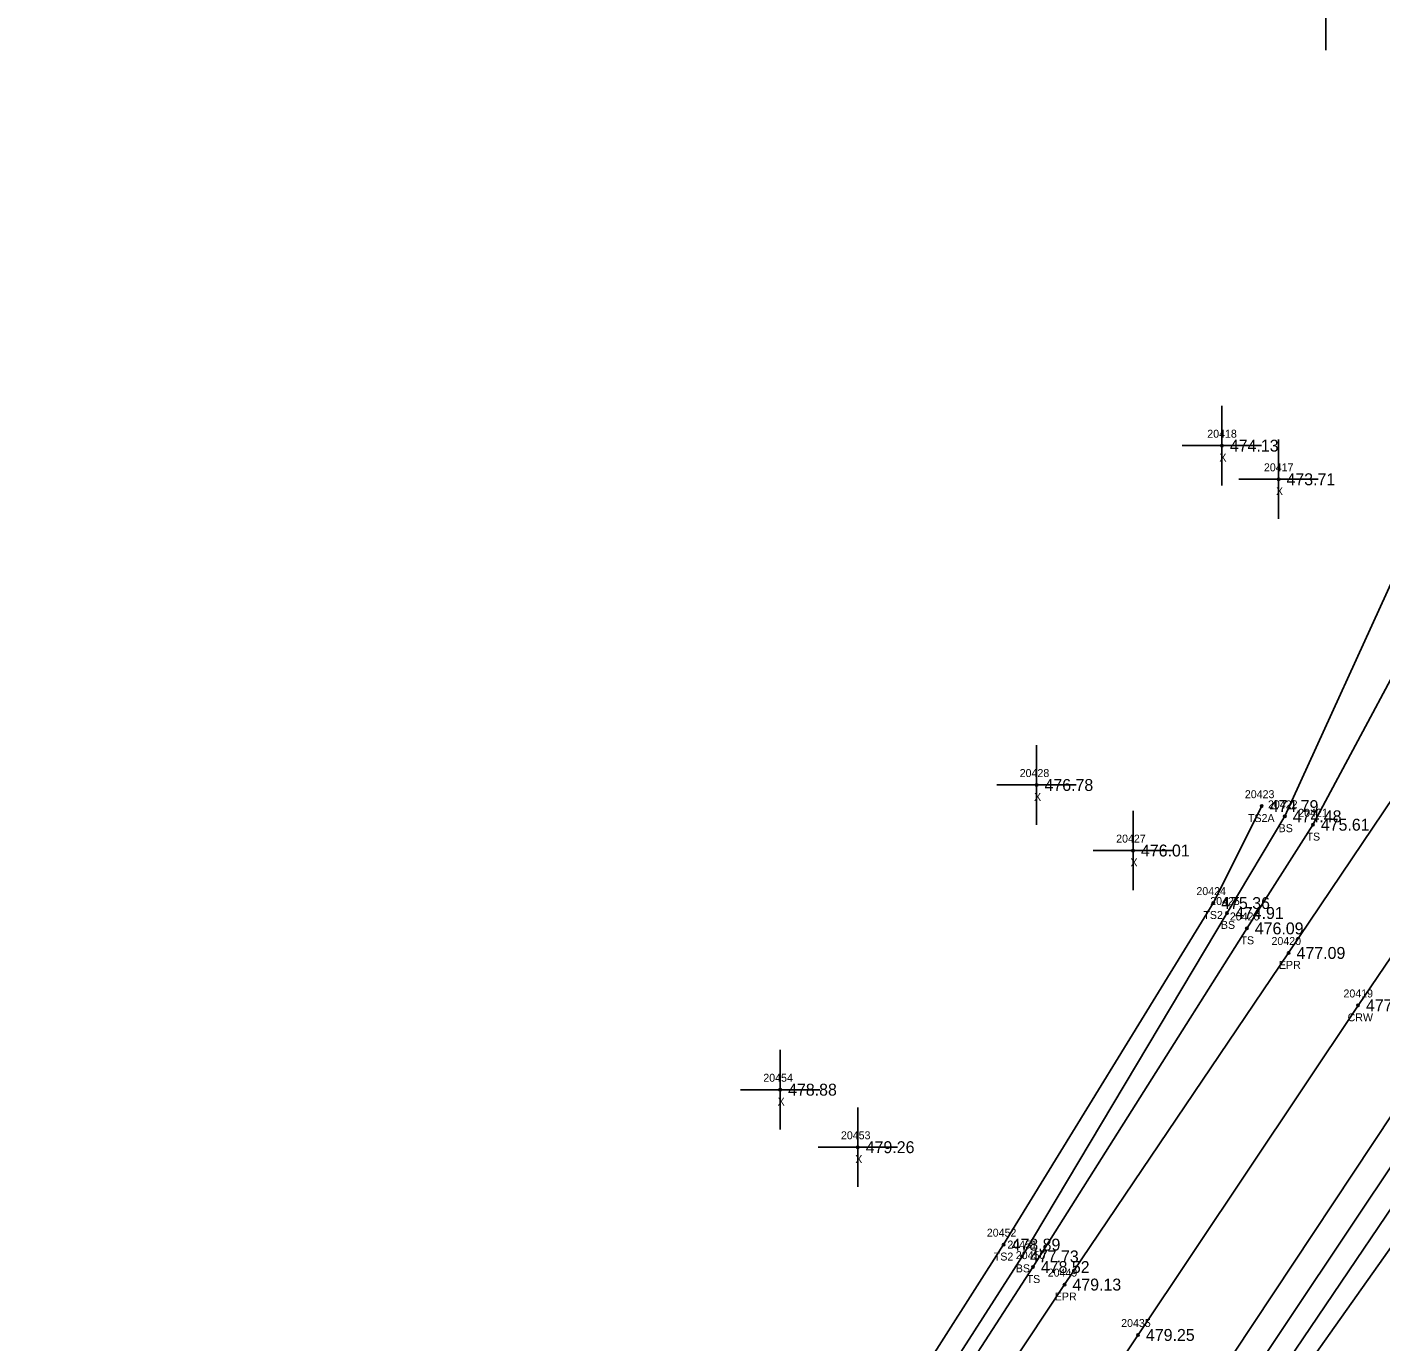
# Model space of a CAD drawing. Extents: x 1741010 to 1742139, y 749382 to 750625.
# Drawn here: x 1741324.2 to 1741494.6, y 749875.8 to 750041.3 of the extents above; entities that cross this region are included whole.
import ezdxf

# ---------------------------------------------------------------- set-up
doc = ezdxf.new("R2010")
doc.units = 0
for name, color, linetype in [('RD_DTM_BkLn1', 7, 'Continuous'), ('RD_DTM_BkLn2', 7, 'Continuous'), ('RD_DTM_BkLn_txCode', 7, 'Continuous'), ('RD_EX_Misc', 7, 'Continuous'), ('RD_EX_Misc_txCode', 7, 'Continuous'), ('RD_EX_Road', 7, 'Continuous'), ('RD_EX_Road_txCode', 7, 'Continuous'), ('RD_EX_TX_Misc_ELEV', 7, 'Continuous'), ('RD_EX_TX_Road_ELEV', 7, 'Continuous'), ('RD_HC_Survey_ELEV', 7, 'Continuous'), ('RD_HC_Survey_txCode', 7, 'Continuous'), ('RD_SMD_Locator', 7, 'Continuous')]:
    doc.layers.add(name, color=color, linetype=linetype)

msp = doc.modelspace()

# ---------------------------------------------------------------- linework, layer by layer
at = {"layer": 'RD_DTM_BkLn1'}
msp.add_lwpolyline([(1741583.42, 750045.09), (1741578.78, 750039.19), (1741548.6, 749999.46), (1741519.68, 749959.35), (1741491.7, 749918.15), (1741464.01, 749876.67), (1741436.51, 749835.23), (1741409.05, 749793.46), (1741381.95, 749752.07), (1741327.4, 749668.12), (1741273.18, 749584.75), (1741218.51, 749501.3), (1741163.8, 749416.96)], dxfattribs=at)
at = {"layer": 'RD_DTM_BkLn2'}
for points in [[(1741595, 750038.14), (1741574.61, 750056.92), (1741567.17, 750063.05), (1741557.5, 750056.24), (1741528.84, 750013.89), (1741502.42, 749971.51), (1741486.02, 749940.89), (1741477.71, 749927.84), (1741450.78, 749885.21), (1741423.85, 749843.58), (1741396.77, 749800.81), (1741369.66, 749759.51), (1741314.64, 749675.74), (1741265.52, 749598.52), (1741262.68, 749595.73), (1741260.89, 749596.52)], [(1741553.69, 750058.21), (1741524.69, 750017.65), (1741497.38, 749974.6), (1741482.49, 749941.95), (1741475.22, 749929.78), (1741449.41, 749886.55), (1741422.56, 749844.68), (1741395.22, 749801.69), (1741368.2, 749760.22), (1741313.51, 749676.19), (1741261.6, 749597.61)], [(1741595, 750038.14), (1741592, 750028.61), (1741562.19, 749990.08), (1741531.32, 749949.92), (1741504.18, 749910.32), (1741476.42, 749868.74), (1741449.21, 749826.98), (1741421.85, 749784.9), (1741395.46, 749743.34), (1741340.74, 749659.13), (1741287.12, 749574.46), (1741231.7, 749491.89), (1741176.84, 749408.86)], [(1741599.45, 750031.16), (1741593.66, 750027.37), (1741564.55, 749987.86), (1741532.82, 749948.93), (1741506.71, 749908.62), (1741479.05, 749867.73), (1741451.41, 749825.96), (1741424.08, 749783.57), (1741397.6, 749742.18), (1741343.11, 749657.77), (1741289.87, 749573.19), (1741234.86, 749489.33), (1741179.61, 749406.64)], [(1741602.3, 750028.04), (1741596.22, 750024.37), (1741565.72, 749986.92), (1741536.13, 749947.45), (1741509.05, 749906.34), (1741480.78, 749866.4), (1741453.63, 749824.8), (1741427.39, 749781.55), (1741401.53, 749739.33), (1741346.85, 749655.57), (1741291.93, 749571.65), (1741238.4, 749487.04), (1741181.74, 749404.39)], [(1741479.58, 749943.23), (1741473.48, 749931.03), (1741447.1, 749888.04), (1741420.34, 749846.09), (1741393.11, 749803.2), (1741365.38, 749761.79), (1741310.15, 749678.29), (1741258.88, 749601.42), (1741259.49, 749597.6), (1741260.89, 749596.52)]]:
    msp.add_lwpolyline(points, dxfattribs=at)
at = {"layer": 'RD_EX_Misc'}
for p, q in [((1741487.65, 750038.36), (1741487.65, 750048.36)), ((1741474.57, 749983.6), (1741474.57, 749993.6)), ((1741481.7, 749979.37), (1741481.7, 749989.37)), ((1741469.57, 749988.6), (1741479.57, 749988.6)), ((1741476.7, 749984.37), (1741486.7, 749984.37)), ((1741451.24, 749940.89), (1741451.24, 749950.89)), ((1741446.24, 749945.89), (1741456.24, 749945.89)), ((1741463.38, 749932.64), (1741463.38, 749942.64)), ((1741458.38, 749937.64), (1741468.38, 749937.64)), ((1741418.97, 749902.54), (1741418.97, 749912.54)), ((1741413.97, 749907.54), (1741423.97, 749907.54)), ((1741428.74, 749895.3), (1741428.74, 749905.3)), ((1741423.74, 749900.3), (1741433.74, 749900.3))]:
    msp.add_line(p, q, dxfattribs=at)
at = {"layer": 'RD_EX_Road'}
for points in [[(1741574.14, 750053.03), (1741573.09, 750050.35), (1741570.35, 750045.84), (1741539.87, 750005.43), (1741510.87, 749966.19), (1741482.97, 749924.75), (1741454.76, 749883.01), (1741427.14, 749841.37), (1741399.6, 749799.14), (1741372.83, 749758.13), (1741317.93, 749673.6), (1741267.39, 749595.97), (1741263.6, 749591.05), (1741254, 749576.22), (1741209.28, 749507.22), (1741154.74, 749422.71)], [(1741592.65, 750037.91), (1741590.39, 750035.78), (1741587.68, 750032.32), (1741557.76, 749993.29), (1741528.74, 749952.66), (1741501.16, 749912.21), (1741473.5, 749870.53), (1741446.05, 749829.26), (1741418.1, 749787.13), (1741391.18, 749745.79), (1741336.54, 749661.65), (1741282.05, 749578.36), (1741227.71, 749494.6), (1741173.28, 749411)]]:
    msp.add_lwpolyline(points, dxfattribs=at)
at = {"layer": 'RD_SMD_Locator'}
for centre in [(1741474.57, 749988.6), (1741481.7, 749984.37), (1741451.24, 749945.89), (1741479.58, 749943.23), (1741482.49, 749941.95), (1741486.02, 749940.89), (1741463.38, 749937.64), (1741473.48, 749931.03), (1741475.22, 749929.78), (1741477.71, 749927.84), (1741482.97, 749924.75), (1741491.7, 749918.15), (1741418.97, 749907.54), (1741428.74, 749900.3), (1741447.1, 749888.04), (1741449.41, 749886.55), (1741450.78, 749885.21), (1741454.76, 749883.01), (1741464.01, 749876.67)]:
    msp.add_circle(centre, 0.15, dxfattribs=at)

# ---------------------------------------------------------------- texts
at = {"layer": 'RD_DTM_BkLn_txCode'}
for s, p in [('20423', (1741477.46, 749944.23)), ('20422', (1741480.37, 749942.95)), ('20421', (1741484.18, 749941.89)), ('TS2A', (1741477.85, 749941.23)), ('BS', (1741481.71, 749939.95)), ('TS', (1741485.22, 749938.89)), ('20424', (1741471.36, 749932.03)), ('20425', (1741473.1, 749930.78)), ('TS2', (1741472.24, 749929.03)), ('20426', (1741475.57, 749928.84)), ('BS', (1741474.44, 749927.78)), ('TS', (1741476.91, 749925.84)), ('20452', (1741444.98, 749889.04)), ('20451', (1741447.57, 749887.55)), ('TS2', (1741445.86, 749886.04)), ('20450', (1741448.63, 749886.21)), ('BS', (1741448.63, 749884.55)), ('TS', (1741449.99, 749883.21))]:
    msp.add_text(s, height=1, dxfattribs=at).set_placement(p)
at = {"layer": 'RD_EX_Misc_txCode'}
for s, p in [('20418', (1741472.73, 749989.6)), ('X', (1741474.25, 749986.6)), ('20417', (1741479.86, 749985.37)), ('X', (1741481.38, 749982.37)), ('20428', (1741449.12, 749946.89)), ('X', (1741450.93, 749943.89)), ('20427', (1741461.26, 749938.64)), ('X', (1741463.06, 749935.64)), ('20454', (1741416.85, 749908.54)), ('X', (1741418.65, 749905.54)), ('20453', (1741426.62, 749901.3)), ('X', (1741428.42, 749898.3))]:
    msp.add_text(s, height=1, dxfattribs=at).set_placement(p)
at = {"layer": 'RD_EX_Road_txCode'}
for s, p in [('20420', (1741480.81, 749925.75)), ('EPR', (1741481.74, 749922.75)), ('20449', (1741452.65, 749884.01)), ('EPR', (1741453.54, 749881.01))]:
    msp.add_text(s, height=1, dxfattribs=at).set_placement(p)
at = {"layer": 'RD_EX_TX_Misc_ELEV'}
for s, p in [('474.13', (1741475.57, 749987.85)), ('473.71', (1741482.7, 749983.62)), ('476.78', (1741452.24, 749945.14)), ('474.79', (1741480.58, 749942.48)), ('474.48', (1741483.49, 749941.2)), ('475.61', (1741487.02, 749940.14)), ('476.01', (1741464.38, 749936.89)), ('475.36', (1741474.48, 749930.28)), ('474.91', (1741476.22, 749929.03)), ('476.09', (1741478.71, 749927.09)), ('478.88', (1741419.97, 749906.79)), ('479.26', (1741429.74, 749899.55)), ('478.89', (1741448.1, 749887.29)), ('477.73', (1741450.41, 749885.8)), ('478.52', (1741451.78, 749884.46))]:
    msp.add_text(s, height=1.5, dxfattribs=at).set_placement(p)
at = {"layer": 'RD_EX_TX_Road_ELEV'}
for s, p in [('477.09', (1741483.97, 749924)), ('479.13', (1741455.76, 749882.26))]:
    msp.add_text(s, height=1.5, dxfattribs=at).set_placement(p)
at = {"layer": 'RD_HC_Survey_ELEV'}
for s, p in [('477.03', (1741492.7, 749917.4)), ('479.25', (1741465.01, 749875.92))]:
    msp.add_text(s, height=1.5, dxfattribs=at).set_placement(p)
at = {"layer": 'RD_HC_Survey_txCode'}
for s, p in [('20419', (1741489.87, 749919.15)), ('CRW', (1741490.39, 749916.15)), ('20435', (1741461.89, 749877.67))]:
    msp.add_text(s, height=1, dxfattribs=at).set_placement(p)

doc.saveas('drawing.dxf')
